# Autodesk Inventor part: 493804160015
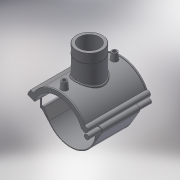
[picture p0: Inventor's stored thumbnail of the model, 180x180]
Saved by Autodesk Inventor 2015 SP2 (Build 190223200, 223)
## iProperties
Created: 2017-07
Part Number: 493804160015
Material: Generic
Description: PLASSON TRANSITION SADDLE 160-1.1/2"
Document SubType Name: Modeling
Designer: KIM
Density: 1 g/cm^3
Appearance: Default
Author: KIM
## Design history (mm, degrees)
derived "493804.ipt"
feature "Solid1::493804.ipt"
tag "TaggingFeature1"
body "Solid1"
other parameters: "B_" = 196, "H_" = 53, "L_" = 118, "d_t" = 6, "G_" = 44.845, "d148" = 2.4, "d160" = 2.4, "d169" = 2.1, "d192" = 4.2, "d1" = 184, "d2" = 196, "d4" = 118, "d5" = 0, "d6" = 0.1, "d8" = 0, "d19" = 6, "d20" = 6, "d21" = 70.8, "d23" = 0, "d24" = 35.4, "d26" = 0, "d27" = 3, "d28" = 3, "d29" = 3, "d30" = 53.33333, "d31" = 6, "d32" = 0, "d33" = 0, "d34" = 0.6, "d40" = 95.68, "d41" = 62.783, "d43" = 0, "d45" = 0, "d47" = 145, "d48" = 58.2985, "d50" = 0, "d70" = 15, "d72" = 0, "d73" = 6, "d75" = 5, "d76" = 0, "d77" = 8, "d79" = 15, "d80" = 47.2, "d82" = 5 deg, "d84" = 4, "d85" = 14, "d86" = 0, "d87" = 3, "d88" = 0, "d89" = 1, "d90" = 1, "d91" = 94.4, "d92" = 0, "d93" = 0.5, "d94" = 84.21053, "d96" = 187.68, "d97" = 2.36, "d98" = 0, "d102" = 1.34535, "d103" = 44.845, "d104" = 31.8, "d105" = 0, "d106" = 35.876, "d108" = 0, "d109" = -17.66667, "d111" = 0.5, "d112" = 0.5, "d113" = 0, "d114" = 0.5, "d117" = 0.44845, "d120" = 140 deg, "d121" = 24.228, "d122" = 20 deg, "d123" = 368, "d124" = 110.4, "d126" = 0, "d143" = 164.8, "d145" = 18.46154, "d149" = 2.4, "d150" = 20.30769, "d153" = 118, "d154" = 0, "d156" = 92, "d157" = 160 deg, "d159" = 4.8, "d161" = 2.4, "d162" = 70.8, "d163" = 0, "d167" = 16, "d168" = 89.7561, "d170" = 2.1, "d172" = 0, "d173" = 1, "d176" = 20 deg, "d177" = 11.2, "d178" = 24, "d180" = 0, "d183" = 9.6, "d184" = 8.96, "d185" = 38.35, "d186" = 38.35, "d187" = 92, "d188" = 7.2, "d189" = 11.2, "d190" = 0, "d191" = 110.4, "d193" = 4.2, "d194" = 2.95, "d195" = 90 deg, "d197" = 0, "d199" = 0
